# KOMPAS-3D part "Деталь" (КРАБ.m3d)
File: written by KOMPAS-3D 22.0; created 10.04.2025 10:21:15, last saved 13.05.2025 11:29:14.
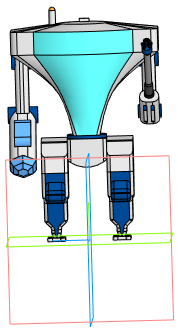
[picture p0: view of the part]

Document properties: Автор: Пользователь Windows; Полное имя файла: C:\Users\Student\Documents\Картошечка\База Сабнатика\КРАБ.m3d

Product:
- Part/product: Деталь
    Масса: 0.18482

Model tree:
1. Эскиз:1
2. Элемент выдавливания:1
     Расстояние 1 = 1
3. Эскиз:2  (with: Элемент выдавливания:1)
4. Элемент выдавливания:2
5. Эскиз:3  (with: Элемент выдавливания:1)
6. Элемент выдавливания:3
     Расстояние 1 = 1
7. Смещенная плоскость:1
     Расстояние = 10
8. Эскиз:4  (with: Элемент выдавливания:3)
9. Элемент выдавливания:4
     Расстояние 1 = 2.75; Расстояние 2 = 2.75
10. Зеркальный массив:2
11. Экземпляр ( 1 )
12. Экземпляр ( 2 )  (with: Элемент выдавливания:1, Элемент выдавливания:4, Элемент выдавливания:2, Элемент выдавливания:3)
13. Элемент выдавливания:5  (with: Элемент выдавливания:4)
     Расстояние 2 = 2.75
14. Эскиз:5  (with: Элемент выдавливания:2)
15. Элемент выдавливания:6
     Расстояние 1 = 3
16. Эскиз:6  (with: Элемент выдавливания:1, Элемент выдавливания:6)
17. Элемент выдавливания:7
     Расстояние 1 = 10
18. Эскиз:7  (with: Элемент выдавливания:6)
19. Элемент выдавливания:8
     Расстояние 1 = 2
20. Эскиз:8  (with: Элемент выдавливания:6)
21. Элемент выдавливания:9
     Расстояние 1 = 2
22. Фаска:1  (with: Элемент выдавливания:8, Элемент выдавливания:9)
     Угол = 45; Длина 1 = 2; Длина 2 = 2
23. Скругление:1  (with: Элемент выдавливания:7, Фаска:1, Элемент выдавливания:9, Элемент выдавливания:8)
     Радиус = 1
24. Скругление:2  (with: Элемент выдавливания:8)
     Радиус = 1
25. Скругление:3  (with: Элемент выдавливания:9)
     Радиус = 1
26. Скругление:5  (with: Элемент выдавливания:6)
     Радиус = 1
27. Зеркальный массив:3  (with: Экземпляр ( 1 ), Экземпляр ( 2 ), Элемент выдавливания:9, Скругление:3, Элемент выдавливания:6, Элемент выдавливания:8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)
28. Эскиз:9  (with: Элемент выдавливания:8)
29. Элемент выдавливания:10
     Расстояние 1 = 8
30. Скругление:6  (with: Элемент выдавливания:10)
     Радиус = 1
31. Скругление:9  (with: Элемент выдавливания:10)
     Радиус = 1
32. Зеркальный массив:4  (with: Экземпляр ( 1 ), Экземпляр ( 2 ), Элемент выдавливания:10, Скругление:6, Скругление:9)
33. Скругление:10  (with: Элемент выдавливания:10)
     Радиус = 1
34. Эскиз:10  (with: Скругление:6, Скругление:2)
35. Элемент выдавливания:11
     Расстояние 1 = 6
36. Скругление:11  (with: Элемент выдавливания:11)
     Радиус = 1
37. Зеркальный массив:5  (with: Экземпляр ( 1 ), Экземпляр ( 2 ), Элемент выдавливания:11, Скругление:11)
38. Смещенная плоскость:2
     Расстояние = 5
39. Эскиз:11  (with: Скругление:10, Скругление:6)
40. Элемент выдавливания:12
     Расстояние 1 = 10
41. Скругление:12  (with: Элемент выдавливания:12)
     Радиус = 1
42. Скругление:13  (with: Элемент выдавливания:12)
     Радиус = 1
43. Элемент выдавливания:13  (with: Элемент выдавливания:12)
     Расстояние 1 = 3
44. Скругление:14  (with: Элемент выдавливания:13)
     Радиус = 1
45. Эскиз:12  (with: Элемент выдавливания:12, Элемент выдавливания:13)
46. Элемент выдавливания:14
     Расстояние 1 = 1
47. Смещенная плоскость:3
     Расстояние = 3.5
48. Эскиз:18  (with: Элемент выдавливания:14, Элемент выдавливания:12, Элемент выдавливания:13)
49. Смещенная плоскость:4  (with: Элемент выдавливания:14)
     Расстояние = 15
50. Смещенная плоскость:5
     Расстояние = 10
51. Эскиз:19  (with: Элемент выдавливания:14)
52. Эскиз:20
53. Элемент по сечениям:1
54. Элемент выдавливания:25  (with: Элемент по сечениям:1)
     Расстояние 1 = 7
55. Эскиз:21  (with: Элемент выдавливания:25)
56. Элемент выдавливания:26
     Расстояние 1 = 7
57. Фаска:2  (with: Элемент выдавливания:26)
     Угол = 54; Длина 1 = 5; Длина 2 = 6.88191
58. Эскиз:22  (with: Элемент выдавливания:26)
59. Элемент выдавливания:27
     Расстояние 1 = 5
60. Эскиз:23  (with: Элемент выдавливания:27)
61. Элемент выдавливания:28
     Расстояние 2 = 3
62. Зеркальный массив:8  (with: Экземпляр ( 1 ), Экземпляр ( 2 ), Элемент выдавливания:28)
63. Смещенная плоскость:6  (with: Элемент выдавливания:25)
     Расстояние = 2
64. Эскиз:24
65. Элемент по сечениям:2  (with: Элемент выдавливания:25)
66. Смещенная плоскость:7
     Расстояние = 59
67. Эскиз:25
68. Элемент выдавливания:29
     Расстояние 1 = 20
69. Эскиз:26  (with: Элемент выдавливания:29)
70. Элемент выдавливания:30
     Расстояние 1 = 1; Расстояние 2 = 9
71. Зеркальный массив:9  (with: Экземпляр ( 1 ), Экземпляр ( 2 ), Элемент выдавливания:29, Элемент выдавливания:30)
72. Эскиз:28  (with: Элемент выдавливания:29)
73. Элемент выдавливания:31
     Расстояние 1 = 2
74. Фаска:3  (with: Элемент выдавливания:31)
     Угол = 45; Длина 1 = 2; Длина 2 = 2
75. Эскиз:29  (with: Фаска:3)
76. Элемент выдавливания:32
     Расстояние 1 = 20
77. Эскиз:35  (with: Элемент выдавливания:32)
78. Элемент выдавливания:36
     Расстояние 1 = 2; Расстояние 2 = 2
79. Скругление:16  (with: Элемент выдавливания:36)
     Радиус = 2
80. Смещенная плоскость:11
     Расстояние = -3
81. Зеркальный массив:10  (with: Экземпляр ( 1 ), Экземпляр ( 2 ), Элемент выдавливания:36, Скругление:16)
82. Эскиз:36  (with: Элемент выдавливания:32)
83. Смещенная плоскость:12  (with: Элемент выдавливания:32)
     Расстояние = 2
84. Эскиз:37  (with: Элемент выдавливания:32)
85. Элемент по сечениям:3
86. Смещенная плоскость:13  (with: Элемент по сечениям:3)
     Расстояние = 1
87. Эскиз:38  (with: Элемент по сечениям:3)
88. Элемент по сечениям:4  (with: Элемент по сечениям:3)
89. Эскиз:40  (with: Элемент выдавливания:29, Элемент выдавливания:32)
90. Элемент выдавливания:38
     Расстояние 1 = 2.5; Расстояние 2 = 6.5
91. Эскиз:41  (with: Элемент выдавливания:29)
92. Элемент выдавливания:39
     Расстояние 1 = 4
93. Эскиз:42  (with: Элемент выдавливания:39)
94. Элемент выдавливания:40
     Расстояние 1 = 3
95. Фаска:5  (with: Элемент выдавливания:40)
     Угол = 45; Длина 1 = 3; Длина 2 = 3
96. Эскиз:43
97. Фаска:6  (with: Элемент выдавливания:39)
     Угол = 42; Длина 1 = 0.7; Длина 2 = 0.630283
98. Эскиз:45  (with: Фаска:5)
99. Элемент выдавливания:42
     Расстояние 1 = 10
100. Эскиз:46  (with: Элемент выдавливания:42)
101. Элемент выдавливания:44
     Расстояние 1 = 1
102. Эскиз:47  (with: Элемент выдавливания:44)
103. Элемент выдавливания:45
     Расстояние 1 = 4
104. Эскиз:48  (with: Элемент выдавливания:45)
105. Элемент выдавливания:46
     Расстояние 1 = 15
106. Скругление:17  (with: Элемент выдавливания:46)
     Радиус = 1
107. Эскиз:49  (with: Элемент выдавливания:46)
108. Элемент выдавливания:47
     Расстояние 1 = 2
109. Скругление:18  (with: Элемент выдавливания:47)
     Радиус = 1
110. Эскиз:50  (with: Элемент выдавливания:47)
111. Элемент выдавливания:48
     Расстояние 1 = 1.5
112. Эскиз:51  (with: Элемент выдавливания:48)
113. Элемент выдавливания:49
     Расстояние 1 = 0.5
114. Эскиз:52  (with: Элемент выдавливания:48)
115. Элемент выдавливания:50
     Расстояние 1 = 0.5
116. Эскиз:53  (with: Элемент выдавливания:48)
117. Элемент выдавливания:51
     Расстояние 1 = 0.5
118. Скругление:19  (with: Элемент выдавливания:51, Элемент выдавливания:49, Элемент выдавливания:50)
     Радиус = 0.2
119. Эскиз:54
120. Элемент выдавливания:52
     Расстояние 1 = 1.5; Расстояние 2 = 5.5
121. Эскиз:55  (with: Элемент по сечениям:2)
122. Элемент выдавливания:53
     Расстояние 1 = 1
123. Скругление:20  (with: Элемент по сечениям:2)
     Радиус = 5
124. Элемент выдавливания:54  (with: Элемент выдавливания:49)
     Расстояние 1 = 0.4
125. Скругление:21  (with: Элемент выдавливания:54)
     Радиус = 0.2
126. Элемент выдавливания:57  (with: Элемент выдавливания:50)
     Расстояние 1 = 0.4
127. Скругление:22  (with: Элемент выдавливания:57)
     Радиус = 0.2
128. Элемент выдавливания:58  (with: Элемент выдавливания:51)
     Расстояние 1 = 0.4
129. Скругление:23  (with: Элемент выдавливания:58)
     Радиус = 0.2
130. Эскиз:56  (with: Элемент по сечениям:2)
131. Элемент выдавливания:59
     Расстояние 1 = 5; Расстояние 2 = 1
132. Скругление:24  (with: Элемент выдавливания:59)
     Радиус = 1
133. Эскиз:57  (with: Элемент выдавливания:42)
134. Элемент выдавливания:60
     Расстояние 1 = 1; Расстояние 2 = 2
135. Скругление:25  (with: Элемент выдавливания:60)
     Радиус = 1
